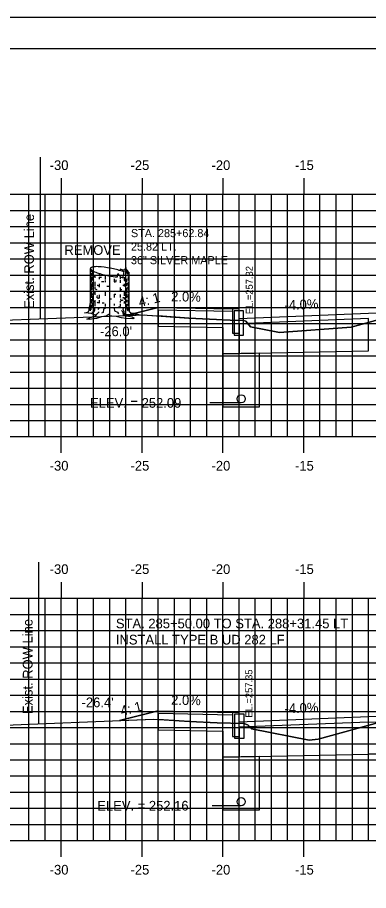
# Model space of a CAD drawing. Extents: x 856680 to 856850, y 366268 to 366378.
# Drawn here: x 856730.4 to 856752.1, y 366324.1 to 366378.2 of the extents above; entities that cross this region are included whole.
import ezdxf

# ---------------------------------------------------------------- set-up
doc = ezdxf.new("R2010")
doc.units = 0
for name, color, linetype in [('ANNOTATION', 7, 'Continuous'), ('BORDER', 7, 'Continuous'), ('D_Curb_Type_1_Lt', 7, 'Continuous'), ('D_Drainage_Text', 7, 'Continuous'), ('D_Roadway_Centerline', 7, 'Continuous'), ('D_Roadway_Edge_Shoulder', 7, 'Continuous'), ('D_Roadway_FinishedGrade', 7, 'Continuous'), ('D_Roadway_Sidewalks_Paved', 7, 'Continuous'), ('D_Roadway_SubGrade', 7, 'Continuous'), ('D_Text_Monospaced', 7, 'Continuous'), ('D_Text_Standard', 7, 'Continuous'), ('E_ROW_Line', 7, 'Continuous'), ('H_V ANNOTATION', 7, 'Continuous'), ('JUNK COM EXC', 7, 'Continuous'), ('JUNK FILL', 7, 'Continuous'), ('junk strct exc', 7, 'Continuous'), ('MAJOR', 7, 'Continuous'), ('MINOR', 7, 'Continuous'), ('PDRAIN', 7, 'Continuous'), ('PLOT BOUNDARY', 7, 'Continuous'), ('S_Curb_Type_2', 7, 'Continuous'), ('S_Roadway_Centerline', 7, 'Continuous'), ('S_Trees_Decid_Pay', 7, 'Continuous')]:
    doc.layers.add(name, color=color, linetype=linetype)

msp = doc.modelspace()

# ---------------------------------------------------------------- linework, layer by layer
at = {"layer": 'BORDER'}
msp.add_line((856848.116, 366376.236), (856688.116, 366376.236), dxfattribs=at)
at = {"layer": 'D_Curb_Type_1_Lt'}
for points in [[(856743.7, 366360.142), (856743.7, 366358.642), (856744.116, 366358.642), (856744.116, 366360.142)], [(856743.7, 366335.174), (856743.7, 366333.674), (856744.116, 366333.674), (856744.116, 366335.174)]]:
    msp.add_lwpolyline(points, close=True, dxfattribs=at)
at = {"layer": 'D_Roadway_Centerline'}
msp.add_lwpolyline([(856752.116, 366334.911), (856763.116, 366335.131), (856774.116, 366334.911)], dxfattribs=at)
at = {"layer": 'D_Roadway_Edge_Shoulder'}
for points in [[(856744.116, 366359.558), (856752.116, 366359.878), (856763.116, 366360.098), (856774.116, 366359.878), (856782.117, 366359.558)], [(856744.116, 366334.591), (856752.116, 366334.911), (856763.116, 366335.131), (856774.116, 366334.911), (856782.117, 366334.591)]]:
    msp.add_lwpolyline(points, dxfattribs=at)
at = {"layer": 'D_Roadway_FinishedGrade'}
for p, q in [((856737.142, 366359.741), (856739.111, 366360.233)), ((856736.724, 366334.669), (856739.111, 366335.266))]:
    msp.add_line(p, q, dxfattribs=at)
at = {"layer": 'D_Roadway_Sidewalks_Paved'}
for points in [[(856739.111, 366360.233), (856743.7, 366360.142), (856743.7, 366359.975), (856739.111, 366360.067)], [(856739.111, 366335.266), (856743.7, 366335.174), (856743.7, 366335.007), (856739.111, 366335.099)]]:
    msp.add_lwpolyline(points, close=True, dxfattribs=at)
at = {"layer": 'D_Roadway_SubGrade'}
for points in [[(856739.111, 366360.067), (856739.111, 366359.067), (856743.116, 366358.987), (856743.116, 366357.365), (856744.116, 366357.385)], [(856739.111, 366335.1), (856739.111, 366334.1), (856743.116, 366334.02), (856743.116, 366332.397), (856744.116, 366332.417)]]:
    msp.add_lwpolyline(points, dxfattribs=at)
for points in [[(856752.116, 366359.545), (856744.116, 366359.225), (856744.116, 366357.385), (856752.116, 366357.545)], [(856752.116, 366332.577), (856752.116, 366334.577), (856763.116, 366334.797), (856774.116, 366334.577), (856774.116, 366332.577), (856763.116, 366332.797)], [(856752.116, 366334.577), (856744.116, 366334.257), (856744.116, 366332.417), (856752.116, 366332.577)]]:
    msp.add_lwpolyline(points, close=True, dxfattribs=at)
at = {"layer": 'D_Text_Standard'}
for points in [[(856744.241, 366354.326), (856742.989, 366354.326), (856742.309, 366354.326)], [(856744.241, 366329.396), (856743.138, 366329.396), (856742.458, 366329.396)]]:
    msp.add_lwpolyline(points, dxfattribs=at)
at = {"layer": 'E_ROW_Line'}
for p, q in [((856731.833, 366359.536), (856731.833, 366369.536)), ((856731.742, 366334.466), (856731.742, 366344.466))]:
    msp.add_line(p, q, dxfattribs=at)
at = {"layer": 'JUNK COM EXC'}
for points in [[(856739.111, 366359.703), (856739.111, 366359.067), (856743.116, 366358.987), (856743.116, 366357.365), (856752.116, 366357.545)], [(856752.995, 366359.558), (856751.037, 366359.015), (856746.617, 366358.682), (856744.809, 366359.032), (856744.528, 366359.379), (856744.394, 366359.43), (856743.558, 366359.443), (856741, 366359.571), (856739.111, 366359.703)], [(856739.111, 366334.737), (856739.111, 366334.1), (856743.116, 366334.02), (856743.116, 366332.397), (856752.116, 366332.577), (856763.116, 366332.797)], [(856752.903, 366334.586), (856749.011, 366333.506), (856748.447, 366333.463), (856744.872, 366334.155), (856744.683, 366334.389), (856744.419, 366334.489), (856742.762, 366334.516), (856741.043, 366334.602), (856739.111, 366334.737)]]:
    msp.add_lwpolyline(points, dxfattribs=at)
at = {"layer": 'JUNK FILL'}
for points in [[(856739.116, 366359.703), (856739.116, 366360.233), (856739.111, 366360.233), (856737.142, 366359.741), (856738.29, 366359.785), (856738.434, 366359.751)], [(856739.116, 366334.737), (856739.116, 366335.266), (856739.111, 366335.266), (856736.724, 366334.669), (856738.85, 366334.756)]]:
    msp.add_lwpolyline(points, close=True, dxfattribs=at)
at = {"layer": 'junk strct exc'}
for points in [[(856743.116, 366357.365), (856743.116, 366354.076), (856745.366, 366354.076), (856745.366, 366357.41)], [(856743.116, 366332.397), (856743.116, 366329.146), (856745.366, 366329.146), (856745.366, 366332.442)]]:
    msp.add_lwpolyline(points, close=True, dxfattribs=at)
at = {"layer": 'MAJOR'}
for p, q in [((856733.116, 366368.238), (856733.116, 366367.236)), ((856738.116, 366368.238), (856738.116, 366367.236)), ((856743.116, 366368.238), (856743.116, 366367.236)), ((856748.116, 366368.238), (856748.116, 366367.236)), ((856693.116, 366367.236), (856833.116, 366367.236)), ((856693.116, 366367.236), (856833.116, 366367.236)), ((856733.116, 366352.236), (856733.116, 366367.236)), ((856738.116, 366352.236), (856738.116, 366367.236)), ((856743.116, 366352.236), (856743.116, 366367.236)), ((856748.116, 366352.236), (856748.116, 366367.236)), ((856693.116, 366362.236), (856833.116, 366362.236)), ((856693.116, 366357.236), (856833.116, 366357.236)), ((856693.116, 366352.236), (856833.116, 366352.236)), ((856693.116, 366352.236), (856833.116, 366352.236)), ((856733.116, 366351.234), (856733.116, 366352.236)), ((856738.116, 366351.234), (856738.116, 366352.236)), ((856743.116, 366351.234), (856743.116, 366352.236)), ((856748.116, 366351.234), (856748.116, 366352.236)), ((856733.116, 366343.238), (856733.116, 366342.236)), ((856738.116, 366343.238), (856738.116, 366342.236)), ((856743.116, 366343.238), (856743.116, 366342.236)), ((856748.116, 366343.238), (856748.116, 366342.236)), ((856693.116, 366342.236), (856833.116, 366342.236)), ((856693.116, 366342.236), (856833.116, 366342.236)), ((856733.116, 366327.236), (856733.116, 366342.236)), ((856738.116, 366327.236), (856738.116, 366342.236)), ((856743.116, 366327.236), (856743.116, 366342.236)), ((856748.116, 366327.236), (856748.116, 366342.236)), ((856693.116, 366337.236), (856833.116, 366337.236)), ((856693.116, 366332.236), (856833.116, 366332.236)), ((856693.116, 366327.236), (856833.116, 366327.236)), ((856693.116, 366327.236), (856833.116, 366327.236)), ((856733.116, 366326.234), (856733.116, 366327.236)), ((856738.116, 366326.234), (856738.116, 366327.236)), ((856743.116, 366326.234), (856743.116, 366327.236)), ((856748.116, 366326.234), (856748.116, 366327.236))]:
    msp.add_line(p, q, dxfattribs=at)
at = {"layer": 'MINOR'}
for p, q in [((856731.116, 366352.236), (856731.116, 366367.236)), ((856732.116, 366352.236), (856732.116, 366367.236)), ((856734.116, 366352.236), (856734.116, 366367.236)), ((856735.116, 366352.236), (856735.116, 366367.236)), ((856736.116, 366352.236), (856736.116, 366367.236)), ((856737.116, 366352.236), (856737.116, 366367.236)), ((856739.116, 366352.236), (856739.116, 366367.236)), ((856740.116, 366352.236), (856740.116, 366367.236)), ((856741.116, 366352.236), (856741.116, 366367.236)), ((856742.116, 366352.236), (856742.116, 366367.236)), ((856744.116, 366352.236), (856744.116, 366367.236)), ((856745.116, 366352.236), (856745.116, 366367.236)), ((856746.116, 366352.236), (856746.116, 366367.236)), ((856747.116, 366352.236), (856747.116, 366367.236)), ((856749.116, 366352.236), (856749.116, 366367.236)), ((856750.116, 366352.236), (856750.116, 366367.236)), ((856751.116, 366352.236), (856751.116, 366367.236)), ((856693.116, 366366.236), (856833.116, 366366.236)), ((856693.116, 366365.236), (856833.116, 366365.236)), ((856693.116, 366364.236), (856833.116, 366364.236)), ((856693.116, 366363.236), (856833.116, 366363.236)), ((856693.116, 366361.236), (856833.116, 366361.236)), ((856693.116, 366360.236), (856833.116, 366360.236)), ((856693.116, 366359.236), (856833.116, 366359.236)), ((856693.116, 366358.236), (856833.116, 366358.236)), ((856693.116, 366356.236), (856833.116, 366356.236)), ((856693.116, 366355.236), (856833.116, 366355.236)), ((856693.116, 366354.236), (856833.116, 366354.236)), ((856693.116, 366353.236), (856833.116, 366353.236)), ((856731.116, 366327.236), (856731.116, 366342.236)), ((856732.116, 366327.236), (856732.116, 366342.236)), ((856734.116, 366327.236), (856734.116, 366342.236)), ((856735.116, 366327.236), (856735.116, 366342.236)), ((856736.116, 366327.236), (856736.116, 366342.236)), ((856737.116, 366327.236), (856737.116, 366342.236)), ((856739.116, 366327.236), (856739.116, 366342.236)), ((856740.116, 366327.236), (856740.116, 366342.236)), ((856741.116, 366327.236), (856741.116, 366342.236)), ((856742.116, 366327.236), (856742.116, 366342.236)), ((856744.116, 366327.236), (856744.116, 366342.236)), ((856745.116, 366327.236), (856745.116, 366342.236)), ((856746.116, 366327.236), (856746.116, 366342.236)), ((856747.116, 366327.236), (856747.116, 366342.236)), ((856749.116, 366327.236), (856749.116, 366342.236)), ((856750.116, 366327.236), (856750.116, 366342.236)), ((856751.116, 366327.236), (856751.116, 366342.236)), ((856752.116, 366327.236), (856752.116, 366342.236)), ((856693.116, 366341.236), (856833.116, 366341.236)), ((856693.116, 366340.236), (856833.116, 366340.236)), ((856693.116, 366339.236), (856833.116, 366339.236)), ((856693.116, 366338.236), (856833.116, 366338.236)), ((856693.116, 366336.236), (856833.116, 366336.236)), ((856693.116, 366335.236), (856833.116, 366335.236)), ((856693.116, 366334.236), (856833.116, 366334.236)), ((856693.116, 366333.236), (856833.116, 366333.236)), ((856693.116, 366331.236), (856833.116, 366331.236)), ((856693.116, 366330.236), (856833.116, 366330.236)), ((856693.116, 366329.236), (856833.116, 366329.236)), ((856693.116, 366328.236), (856833.116, 366328.236))]:
    msp.add_line(p, q, dxfattribs=at)
at = {"layer": 'PDRAIN'}
for points in [[(856743.116, 366357.365), (856743.116, 366354.076), (856745.366, 366354.076), (856745.366, 366357.41)], [(856743.116, 366332.397), (856743.116, 366329.146), (856745.366, 366329.146), (856745.366, 366332.442)]]:
    msp.add_lwpolyline(points, dxfattribs=at)
for centre in [(856744.241, 366354.576), (856744.241, 366329.646)]:
    msp.add_circle(centre, 0.25, dxfattribs=at)
at = {"layer": 'PLOT BOUNDARY'}
msp.add_lwpolyline([(856680.023, 366268.177), (856850.023, 366268.177), (856850.023, 366378.177), (856680.023, 366378.177)], close=True, dxfattribs=at)
at = {"layer": 'S_Curb_Type_2'}
for points in [[(856744.394, 366360.013), (856743.811, 366360.013), (856743.811, 366358.513), (856744.394, 366358.513)], [(856744.419, 366335.072), (856743.836, 366335.072), (856743.836, 366333.572), (856744.419, 366333.572)]]:
    msp.add_lwpolyline(points, close=True, dxfattribs=at)
at = {"layer": 'S_Roadway_Centerline'}
for points in [[(856722.996, 366359.194), (856738.29, 366359.785), (856738.434, 366359.751), (856741, 366359.571), (856743.558, 366359.443), (856744.394, 366359.43), (856744.528, 366359.379), (856744.809, 366359.032), (856746.617, 366358.682), (856751.037, 366359.015), (856752.995, 366359.558)], [(856728.575, 366334.337), (856738.85, 366334.756), (856741.043, 366334.602), (856742.762, 366334.516), (856744.419, 366334.489), (856744.683, 366334.389), (856744.872, 366334.155), (856748.447, 366333.463), (856749.011, 366333.506), (856752.903, 366334.586)]]:
    msp.add_lwpolyline(points, dxfattribs=at)
at = {"layer": 'S_Trees_Decid_Pay'}
for p, q in [((856734.974, 366362.551), (856734.974, 366362.431)), ((856734.974, 366362.379), (856734.974, 366362.165)), ((856735.054, 366362.507), (856735.054, 366362.253)), ((856735.459, 366362.34), (856735.459, 366362.253)), ((856737.099, 366362.348), (856737.099, 366362.173)), ((856734.974, 366362.12), (856734.974, 366361.782)), ((856735.054, 366362.157), (856735.054, 366361.893)), ((856735.054, 366361.796), (856735.054, 366361.488)), ((856735.186, 366362.253), (856735.186, 366362.062)), ((856735.186, 366361.811), (856735.186, 366361.533)), ((856735.459, 366362.112), (856735.459, 366361.973)), ((856735.842, 366362.239), (856735.842, 366361.959)), ((856735.842, 366361.893), (856735.842, 366361.79)), ((856736.388, 366362.002), (856736.388, 366361.822)), ((856736.515, 366361.83), (856736.509, 366361.937)), ((856736.753, 366362.101), (856736.753, 366361.982)), ((856736.753, 366361.93), (856736.753, 366361.745)), ((856737.014, 366362.099), (856737.014, 366361.895)), ((856737.162, 366362.002), (856737.162, 366361.79)), ((856737.162, 366361.725), (856737.162, 366361.576)), ((856737.248, 366362.148), (856737.248, 366361.893)), ((856737.248, 366361.796), (856737.248, 366361.327)), ((856734.974, 366361.665), (856734.974, 366361.304)), ((856734.974, 366361.267), (856734.974, 366360.818)), ((856735.054, 366361.399), (856735.054, 366361.333)), ((856735.186, 366361.488), (856735.186, 366361.379)), ((856735.186, 366361.244), (856735.186, 366361.016)), ((856735.459, 366361.687), (856735.459, 366361.496)), ((856735.842, 366361.179), (856735.842, 366360.958)), ((856736.753, 366361.459), (856736.753, 366361.23)), ((856737.014, 366361.687), (856737.014, 366361.533)), ((856737.162, 366361.399), (856737.162, 366361.099)), ((856737.248, 366361.276), (856737.248, 366361.142)), ((856734.974, 366360.753), (856734.974, 366360.471)), ((856735.054, 366361.099), (856735.054, 366361.001)), ((856735.054, 366360.95), (856735.054, 366360.59)), ((856735.186, 366360.687), (856735.186, 366360.303)), ((856735.459, 366361.016), (856735.459, 366360.808)), ((856735.459, 366360.687), (856735.459, 366360.487)), ((856736.388, 366361.044), (856736.388, 366360.847)), ((856736.753, 366361.032), (856736.753, 366360.847)), ((856737.014, 366361.17), (856737.014, 366360.95)), ((856737.014, 366360.851), (856737.014, 366360.73)), ((856737.162, 366361.061), (856737.162, 366360.818)), ((856737.162, 366360.708), (856737.162, 366360.567)), ((856737.248, 366361.084), (856737.248, 366360.759)), ((856737.248, 366360.73), (856737.248, 366360.31)), ((856735.054, 366360.538), (856735.054, 366360.372)), ((856735.463, 366360.23), (856735.383, 366360.098)), ((856735.842, 366360.458), (856735.842, 366360.285)), ((856736.388, 366360.464), (856736.388, 366360.361)), ((856736.753, 366360.612), (856736.753, 366360.536)), ((856736.753, 366360.458), (856736.753, 366360.285)), ((856737.014, 366360.579), (856737.014, 366360.48)), ((856737.162, 366360.435), (856737.162, 366360.279)), ((856737.245, 366360.207), (856737.259, 366360.089))]:
    msp.add_line(p, q, dxfattribs=at)
for points in [[(856737.299, 366362.422), (856737.299, 366360.285), (856737.319, 366360.143), (856737.325, 366360.017), (856737.368, 366359.931), (856737.461, 366359.881), (856737.597, 366359.881), (856737.84, 366359.826), (856738.007, 366359.776), (856737.864, 366359.746), (856737.627, 366359.783), (856737.417, 366359.771), (856737.156, 366359.776), (856737.032, 366359.795), (856737.002, 366359.752), (856736.94, 366359.795), (856737.039, 366359.727), (856737.274, 366359.702), (856737.504, 366359.641), (856737.634, 366359.57), (856737.535, 366359.527), (856737.113, 366359.546), (856736.835, 366359.589), (856736.536, 366359.666), (856736.25, 366359.702), (856736.145, 366359.702), (856736.127, 366359.783), (856736.059, 366359.789), (856735.892, 366359.702), (856735.606, 366359.647), (856735.307, 366359.54), (856734.848, 366359.49), (856734.694, 366359.503), (856735.036, 366359.653), (856735.239, 366359.684), (856735.227, 366359.758), (856734.967, 366359.857), (856734.792, 366359.888), (856734.551, 366359.9), (856734.749, 366359.937), (856734.811, 366359.974), (856734.835, 366360.061), (856734.848, 366360.23), (856734.893, 366360.316), (856734.921, 366360.557), (856734.921, 366362.643)], [(856736.781, 366362.099), (856736.744, 366362.202), (856736.679, 366362.208), (856736.679, 366362.29), (856736.604, 366362.297), (856736.58, 366362.116)], [(856736.92, 366362.461), (856736.899, 366362.568), (856736.767, 366362.599), (856736.76, 366362.511)], [(856736.942, 366362.095), (856736.95, 366362.239), (856736.996, 366362.231), (856737.01, 366362.606), (856737.104, 366362.614), (856737.119, 366362.694), (856737.156, 366362.356), (856737.202, 366362.451), (856737.222, 366362.297), (856737.299, 366362.422), (856737.293, 366362.232)], [(856737.299, 366362.422), (856737.253, 366362.445), (856737.23, 366362.511), (856737.179, 366362.534), (856737.145, 366362.459)], [(856735.345, 366360.822), (856735.347, 366360.898), (856735.354, 366360.965)], [(856736.891, 366360.73), (856736.899, 366360.656), (856736.825, 366360.65), (856736.81, 366360.767)], [(856734.972, 366360.398), (856734.912, 366360.238), (856734.898, 366360.112), (856734.906, 366360.015)], [(856735.029, 366360.318), (856734.957, 366360.215), (856734.957, 366360.089)], [(856735.169, 366360.244), (856735.169, 366360.038), (856735.112, 366359.929), (856735.015, 366359.912)], [(856735.824, 366360.169), (856735.721, 366360.118), (856735.707, 366359.912), (856735.604, 366359.883)], [(856736.39, 366360.178), (856736.407, 366360.024), (856736.604, 366359.943), (856736.65, 366359.84)], [(856737.032, 366359.795), (856737.014, 366359.974), (856736.952, 366360.11), (856736.959, 366360.211)], [(856737.179, 366360.215), (856737.185, 366360.089), (856737.267, 366359.995)], [(856735.239, 366359.684), (856735.326, 366359.826), (856735.457, 366359.968)], [(856736.841, 366360.042), (856736.915, 366359.974), (856736.934, 366359.876), (856736.94, 366359.795)]]:
    msp.add_lwpolyline(points, dxfattribs=at)
for centre, radius, start, end in [((856734.968, 366362.643), 0.0467, 169.2221, 180.9043), ((856734.976, 366362.643), 0.0544, 180.9043, 191.7221), ((856734.976, 366362.316), 0.0554, 191.6815, 202.5), ((856734.968, 366362.643), 0.0467, 157.54, 169.2221), ((856734.986, 366362.645), 0.0645, 191.7221, 204.3989), ((856734.985, 366362.32), 0.0657, 202.5, 215.1737), ((856734.975, 366362.64), 0.0544, 146.7221, 157.54), ((856735.024, 366362.663), 0.107, 204.3989, 214.2221), ((856734.984, 366362.634), 0.0645, 134.0453, 146.7221), ((856735.02, 366362.345), 0.109, 215.1737, 225), ((856735.071, 366362.694), 0.164, 214.2221, 228.4286), ((856735.013, 366362.604), 0.107, 124.2221, 134.0453), ((856735.061, 366362.386), 0.166, 225, 238.33), ((856735.045, 366362.557), 0.164, 110.0157, 124.2221), ((856735.281, 366362.931), 0.48, 228.4286, 236.7221), ((856735.153, 366362.26), 0.48, 101.7221, 110.0157), ((856735.731, 366363.616), 1.299, 236.7221, 252.1387), ((856735.32, 366361.457), 1.299, 86.3056, 101.7221), ((856737.211, 366368.21), 6.126, 252.1387, 259.2221), ((856735.009, 366356.641), 6.126, 79.2221, 86.3056), ((856735.009, 366356.641), 6.126, 72.1387, 79.2221), ((856736.489, 366361.235), 1.299, 66.6931, 72.1387), ((856734.977, 366362.055), 0.0554, 191.6815, 202.5), ((856734.986, 366362.059), 0.0657, 202.5, 215.1737), ((856735.021, 366362.084), 0.109, 215.1737, 225), ((856735.062, 366362.125), 0.166, 225, 239.1924), ((856735.062, 366361.861), 0.166, 238.3999, 239.1924), ((856735.225, 366362.398), 0.484, 239.1924, 242.5838), ((856735.225, 366362.134), 0.484, 239.1924, 247.5), ((856735.534, 366363.144), 1.292, 247.5, 251.9171), ((856735.533, 366363.405), 1.292, 250.9084, 254.4349), ((856736.109, 366367.993), 5.916, 263.6913, 265.0485), ((856736.11, 366367.732), 5.916, 265.1076, 266.4618), ((856737.211, 366368.21), 6.126, 259.2221, 264.0853), ((856736.11, 366367.732), 5.916, 272.6957, 273.9224), ((856737.211, 366368.21), 6.126, 265.9754, 266.3056), ((856736.9, 366363.393), 1.299, 266.3056, 271.8711), ((856736.686, 366363.144), 1.292, 284.7144, 289.3881), ((856736.995, 366362.134), 0.484, 292.5, 300.8076), ((856737.158, 366362.125), 0.166, 300.8076, 315), ((856737.158, 366361.861), 0.166, 300.8076, 302.9622), ((856737.198, 366362.084), 0.109, 315, 324.8263), ((856737.234, 366362.059), 0.0657, 324.8263, 337.5), ((856737.243, 366362.055), 0.0554, 337.5, 348.3185), ((856737.251, 366362.054), 0.0476, 348.3185, 0), ((856734.977, 366361.534), 0.0554, 191.6815, 202.5), ((856734.977, 366361.277), 0.0554, 191.6815, 202.5), ((856734.986, 366361.538), 0.0657, 202.5, 215.1737), ((856734.986, 366361.281), 0.0657, 202.5, 215.1737), ((856735.021, 366361.563), 0.109, 215.1737, 225), ((856735.021, 366361.306), 0.109, 215.1737, 225), ((856735.062, 366361.604), 0.166, 225, 239.1924), ((856735.062, 366361.347), 0.166, 225, 237.9306), ((856735.225, 366361.877), 0.484, 239.1924, 245.3628), ((856735.534, 366362.881), 1.292, 247.5, 248.1929), ((856735.534, 366362.623), 1.292, 254.3895, 260.7435), ((856735.534, 366362.881), 1.292, 261.6338, 262.8454), ((856736.11, 366367.468), 5.916, 262.8454, 263.6816), ((856736.11, 366367.468), 5.916, 268.2292, 269.8838), ((856736.11, 366367.211), 5.916, 276.2405, 277.1546), ((856736.686, 366362.623), 1.292, 277.1546, 278.1274), ((856736.686, 366362.881), 1.292, 280.7368, 284.7144), ((856736.686, 366362.623), 1.292, 291.5158, 292.5), ((856736.686, 366362.881), 1.292, 291.6463, 292.5), ((856736.995, 366361.877), 0.484, 294.2275, 300.8076), ((856737.158, 366361.604), 0.166, 300.8076, 315), ((856737.158, 366361.347), 0.166, 300.8076, 315), ((856737.198, 366361.563), 0.109, 315, 324.8263), ((856737.198, 366361.306), 0.109, 315, 324.8263), ((856737.234, 366361.538), 0.0657, 324.8263, 337.5), ((856737.234, 366361.281), 0.0657, 324.8263, 337.5), ((856737.243, 366361.534), 0.0554, 337.5, 348.3185), ((856737.243, 366361.277), 0.0554, 337.5, 348.3185), ((856737.251, 366361.533), 0.0476, 348.3185, 0), ((856737.251, 366361.275), 0.0476, 348.3185, 0), ((856734.977, 366361.011), 0.0554, 191.6815, 202.5), ((856734.977, 366360.74), 0.0554, 191.6815, 202.5), ((856734.986, 366360.744), 0.0657, 202.5, 215.1737), ((856735.021, 366360.769), 0.109, 215.1737, 225), ((856735.062, 366360.809), 0.166, 225, 237.9306), ((856735.062, 366361.081), 0.166, 237.9306, 239.1924), ((856735.225, 366361.354), 0.484, 239.1924, 247.5), ((856735.534, 366362.366), 1.292, 249.8999, 254.3895), ((856735.534, 366362.1), 1.292, 261.6205, 262.8454), ((856736.11, 366366.688), 5.916, 262.8454, 263.6816), ((856736.11, 366366.688), 5.916, 269.7243, 270), ((856736.11, 366366.688), 5.916, 270, 271.0793), ((856736.11, 366366.954), 5.916, 272.6957, 273.7279), ((856736.686, 366362.1), 1.292, 280.7537, 284.7144), ((856736.686, 366362.366), 1.292, 288.201, 292.5), ((856736.686, 366362.1), 1.292, 291.6463, 292.5), ((856736.995, 366361.354), 0.484, 292.5, 300.8076), ((856736.995, 366361.082), 0.484, 292.5, 297.266), ((856737.158, 366361.081), 0.166, 300.8076, 315), ((856737.198, 366361.04), 0.109, 315, 324.8263), ((856737.234, 366361.015), 0.0657, 324.8263, 337.5), ((856737.243, 366361.011), 0.0554, 337.5, 348.3185), ((856737.251, 366361.01), 0.0476, 348.3185, 0), ((856735.225, 366360.825), 0.484, 243.4501, 247.5), ((856735.525, 366361.575), 1.292, 247.9396, 248.6304), ((856735.534, 366361.828), 1.292, 250.8466, 254.3895), ((856735.534, 366361.828), 1.292, 261.6338, 262.8454), ((856736.11, 366366.416), 5.916, 262.8454, 263.6816), ((856736.11, 366366.416), 5.916, 265.539, 266.7363), ((856736.11, 366366.159), 5.916, 275.2344, 276.2169), ((856736.686, 366361.828), 1.292, 284.7144, 288.6336), ((856736.686, 366361.571), 1.292, 291.6463, 292.5), ((856736.995, 366360.825), 0.484, 292.5, 300.8076), ((856737.158, 366360.552), 0.166, 300.8076, 315), ((856737.198, 366360.511), 0.109, 315, 324.8263), ((856737.234, 366360.486), 0.0657, 324.8263, 337.5), ((856737.243, 366360.482), 0.0554, 337.5, 348.3185), ((856737.251, 366360.481), 0.0476, 348.3185, 0)]:
    msp.add_arc(centre, radius, start, end, dxfattribs=at)

# ---------------------------------------------------------------- texts
at = {"layer": 'ANNOTATION'}
msp.add_text('REMOVE', height=0.6, dxfattribs=at).set_placement((856733.315, 366363.484))
for s, rotation, p in [('2.0%', 358.8542, (856739.909, 366360.618)), ('4: 1', 14.0362, (856737.975, 366360.259)), ('-4.0%', 2.2906, (856746.932, 366360.072)), ('4: 1', 14.0362, (856736.857, 366334.958)), ('2.0%', 358.8542, (856739.909, 366335.65)), ('-4.0%', 2.2906, (856746.932, 366335.104))]:
    msp.add_text(s, height=0.6, rotation=rotation, dxfattribs=at).set_placement(p)
at = {"layer": 'D_Drainage_Text'}
for s, p in [('STA. 285+50.00 TO STA. 288+31.45 LT', (856736.497, 366340.374)), ('INSTALL TYPE B UD 282 LF', (856736.497, 366339.374))]:
    msp.add_text(s, height=0.6, dxfattribs=at).set_placement(p)
at = {"layer": 'D_Text_Monospaced'}
for s, height, p in [('STA. 285+62.84', 0.49998, (856737.428, 366364.582)), ('25.82 LT.', 0.5, (856737.428, 366363.748)), ('36" SILVER MAPLE', 0.49998, (856737.428, 366362.908))]:
    msp.add_text(s, height=height, dxfattribs=at).set_placement(p)
at = {"layer": 'D_Text_Standard'}
for s, p in [(' EL.=257.32', (856744.963, 366359.652)), (' EL.=257.35', (856744.937, 366334.685))]:
    msp.add_text(s, height=0.4335, rotation=90, dxfattribs=at).set_placement(p)
for s, p in [("-26.0'", (856735.513, 366358.454)), ('ELEV. = 252.09', (856734.898, 366354.026)), ("-26.4'", (856734.374, 366335.492)), ('ELEV. = 252.16', (856735.347, 366329.096))]:
    msp.add_text(s, height=0.6, dxfattribs=at).set_placement(p)
at = {"layer": 'E_ROW_Line'}
for p in [(856731.433, 366360.136), (856731.342, 366335.066)]:
    msp.add_text('Exist. ROW Line', height=0.6, rotation=90, dxfattribs=at).set_placement(p)
at = {"layer": 'H_V ANNOTATION'}
for s, p in [('-30', (856732.404, 366368.736)), ('-25', (856737.402, 366368.736)), ('-20', (856742.41, 366368.736)), ('-15', (856747.573, 366368.736)), ('-30', (856732.404, 366350.136)), ('-25', (856737.402, 366350.136)), ('-20', (856742.41, 366350.136)), ('-15', (856747.573, 366350.136)), ('-30', (856732.404, 366343.736)), ('-25', (856737.402, 366343.736)), ('-20', (856742.41, 366343.736)), ('-15', (856747.573, 366343.736)), ('-30', (856732.404, 366325.136)), ('-25', (856737.402, 366325.136)), ('-20', (856742.41, 366325.136)), ('-15', (856747.573, 366325.136))]:
    msp.add_text(s, height=0.6, dxfattribs=at).set_placement(p)

doc.saveas('drawing.dxf')
